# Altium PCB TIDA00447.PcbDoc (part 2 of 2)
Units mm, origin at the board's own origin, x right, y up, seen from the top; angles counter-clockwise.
Board outline 98 x 65 mm, 2 copper layers (Top Layer, Bottom Layer); 127 components, 100 nets, 389 pads, 331 vias.
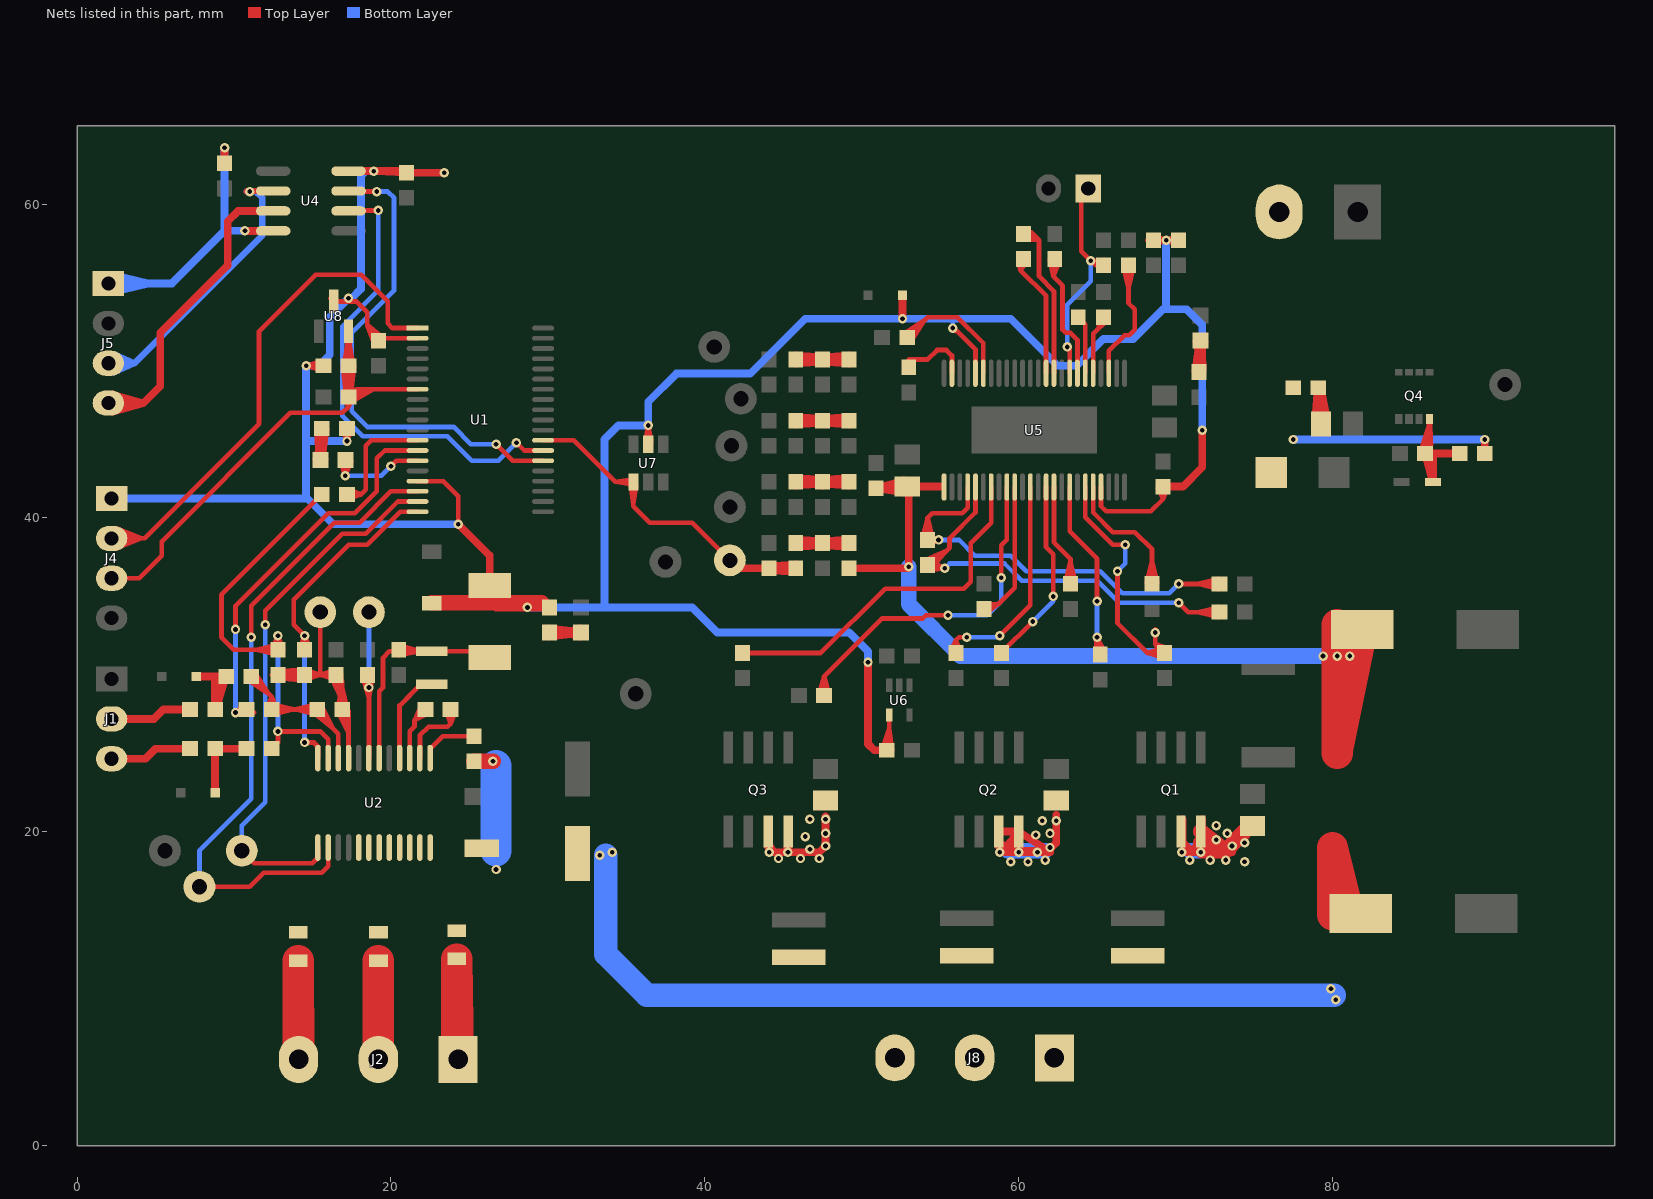
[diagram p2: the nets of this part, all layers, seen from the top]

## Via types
v1: diameter 0.6, hole 0.3, Top Layer to Bottom Layer, 323 vias
v2: diameter 0.5, hole 0.2, Top Layer to Bottom Layer, tented top, 8 vias

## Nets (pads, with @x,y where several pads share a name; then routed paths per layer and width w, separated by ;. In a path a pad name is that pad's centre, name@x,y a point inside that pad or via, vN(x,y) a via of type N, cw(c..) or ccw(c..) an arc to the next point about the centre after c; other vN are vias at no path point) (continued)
M1_SN1: C27.1 R8.1 U5.29 | length 42.9
  Top Layer w0.3: C27.1@54.037,37.306 55.422,37.922 ; C27.1@54.196,36.65 v1(55.3,36.8) ; C27.1@54.2,36.975 v1(55.3,36.8) ; C27.1@54.2,37 54.5,37.3 54.8,37.3 ; C27.1@54.297,37.285 v1(55.3,36.8) ; C27.1@54.419,36.785 55.422,37.922 ; C27.1@54.6,36.8 v1(55.3,36.8) ; U5.29@57.25,41.25 57.25,40.35 ; U5.29@57.25,41.975 57.25,40.35 ; v1(70.2,34.6) 70.8,34 R8.1@72.8,34 ; R8.1@72.737,33.677 71.4,34 ; R8.1@72.737,34.323 71.4,34 ; R8.1@72.775,34 71.4,34 ; C27.1@54.2,37.025 54.8,37.3 ; C27.1@54.2,37.025 55.422,37.922 ; C27.1@54.2,37.025 54.8,37.3 ; 54.8,37.3 54.404,36.772 54.8,37.3 ; 54.8,37.3 54.141,37.345 54.8,37.3 ; 54.8,37.3 55.6,38.1 55.6,38.7 57.25,40.35
  Bottom Layer w0.3: v1(55.3,36.8) 55.6,37.1 59.1,37.1 60.2,36 65,36 66.4,34.6 v1(70.2,34.6)
M1_SP1: C27.2 R10.1 U5.28 | length 36.1
  Top Layer w0.3: C27.2@53.877,38.663 54.2,40 ; C27.2@54.2,38.625 54.2,40 ; C27.2@54.275,38.284 v1(54.9,38.6) ; C27.2@54.275,38.916 v1(54.9,38.6) ; C27.2@54.523,38.663 54.2,40 ; U5.28@56.75,41.25 56.75,40.65 ; U5.28@56.75,41.975 56.75,40.65 ; v1(70.2,35.8) R10.1@72.8,35.8 ; R10.1@72.737,35.477 71.4,35.8 ; R10.1@72.737,36.123 71.4,35.8 ; R10.1@72.775,35.8 71.4,35.8 ; 54.2,40 54.5,40.3 56.4,40.3 56.75,40.65 ; 54.2,40 C27.2@54.2,38.6 v1(54.9,38.6)
  Bottom Layer w0.3: v1(54.9,38.6) 56.2,38.6 57.2,37.6 59.5,37.6 60.5,36.6 65.2,36.6 66.6,35.2 69.6,35.2 v1(70.2,35.8)
M2_DIR: TP4.1 U1.17 U2.14 | length 44.4
  Top Layer w0.3: TP4.1@7.8,16.5 11,16.5 11.9,17.4 15.6,17.4 16,17.8 ; v1(11.1,32.4) 11.1,34.4 16.4,39.7 18,39.7 20,41.7 U1.17@21.7,41.7 ; U2.14@16,18.325 16,17.8 ; U2.14@16,19 16,17.8 ; 20.1,41.7 U1.17@21.15,41.7
  Bottom Layer w0.3: TP4.1@7.8,16.5 7.8,18.8 11.1,22.1 v1(11.1,32.4)
M2_FG: R4.1 U1.19 U2.12 | length 25.8
  Top Layer w0.3: R4.1@14.181,31.685 v1(14.5,32.5) ; v1(14.5,25.7) 15.1,25.7 ; R4.1@14.5,31.6 v1(14.5,32.5) ; R4.1@14.5,31.625 v1(14.5,32.5) ; R4.1@14.819,31.685 v1(14.5,32.5) ; U2.12@15.35,24.7 15.35,25.45 15.1,25.7 ; U2.12@15.35,25.375 15.1,25.7 ; U1.19@21.15,40.4 20.6,40.4 ; U1.19@21.7,40.4 20.6,40.4 ; v1(14.5,32.5) 13.8,33.2 13.8,34.8 17.3,38.3 18.5,38.3 20.6,40.4
  Bottom Layer w0.3: v1(14.5,25.7) v1(14.5,32.5)
M2_SCL: R6.1 U1.13 | length 28.1
  Top Layer w0.3: v1(10.1,32.9) 10.1,34.4 16,40.3 17.7,40.3 19.1,41.7 19.1,43.8 19.6,44.3 U1.13@21.7,44.3 ; R6.1@10.613,28.082 v1(10.1,27.6) ; R6.1@10.775,27.8 v1(10.1,27.6) ; R6.1@10.793,27.475 v1(10.1,27.6) ; R6.1@11.3,27.6 v1(10.1,27.6) ; 20.1,44.3 U1.13@21.15,44.3
  Bottom Layer w0.3: v1(10.1,27.6) v1(10.1,32.9)
M2_SDA: R5.1 U1.12 | length 11.2
  Top Layer w0.3: R5.1@17.2,41.5 18.1,41.5 ; R5.1@17.225,41.5 18.1,41.5 ; R5.1@17.285,41.181 18.1,41.5 ; R5.1@17.285,41.819 18.1,41.5 ; 20.1,44.95 U1.12@21.15,44.95 ; U1.12@21.7,44.95 18.75,44.95 18.4,44.6 18.4,41.8 18.1,41.5
M2_SPEED: TP5.1 U1.18 U2.13 | length 35.7
  Top Layer w0.3: TP5.1@10.5,18.8 11.3,18 15,18 ; v1(12,33.2) 12,34.1 16.9,39 18.4,39 20.45,41.05 ; U2.13@15.35,18.325 15,18 ; U2.13@15.35,19 15.35,18.35 15,18 ; U1.18@21.15,41.05 20.45,41.05 ; U1.18@21.7,41.05 20.45,41.05
  Bottom Layer w0.3: TP5.1@10.5,18.8 10.5,20.4 12,21.9 v1(12,33.2)
M2_U: J2.3 L4.2 | length 24.1
  Top Layer w2: J2.3@14.12,5.5 J2.3@14.1,5.52 ; J2.3@14.1,5.52 L4.2@14.1,11.8 ; J2.3@14.1,5.52 14.1,11.2 ; 14.1,11.2 14.12,5.75 L4.2@14.1,11.8 ; 14.1,11.2 L4.2@14.1,11.8
M2_V: J2.2 L3.2 | length 24.1
  Top Layer w2: 19.2,11.2 19.2,5.75 L3.2@19.2,11.8 ; 19.2,11.2 L3.2@19.2,11.8 ; 19.2,11.2 J2.2@19.2,5.5 L3.2@19.2,11.8
M2_W: J2.1 L2.2 | length 24.4
  Top Layer w2: J2.1@24.28,5.5 J2.1@24.2,5.58 ; J2.1@24.2,5.58 L2.2@24.2,11.9 ; J2.1@24.2,5.58 24.2,11.2 ; 24.2,11.2 24.28,5.75 L2.2@24.2,11.9 ; 24.2,11.2 L2.2@24.2,11.9
NetC4_2: C4.2 U2.1 | length 3.7
  Top Layer w0.3: U2.1@22.5,24.7 22.5,25.3 23.3,26.1 C4.2@25.3,26.1
NetC5_1: C5.1 U2.2 | length 8.1
  Top Layer w0.3: U2.2@21.85,24.7 21.85,26.15 ; U2.2@21.85,25.375 21.85,26.15 ; C5.1@23.48,27.741 23.8,26.9 ; C5.1@24.12,27.741 23.8,26.9 ; 21.85,26.15 22.4,26.7 23.6,26.7 23.8,26.9 ; 23.8,26.9 C5.1@23.8,27.8 23.8,26.9
NetC5_2: C5.2 U2.3 | length 6.8
  Top Layer w0.3: C5.2@21.907,27.983 21.5,27.1 ; C5.2@22.175,27.8 21.5,27.1 ; C5.2@22.2,27.8 21.5,27.1 ; C5.2@22.368,27.538 21.5,27.1 ; 21.2,26.4 21.2,25.375 21.2,25.6 21.2,26.4 ; 21.2,26.4 21.5,26.7 21.5,27.1
NetC7_2: C7.2 TP3.1 U2.7 | length 15.4
  Top Layer w0.3: C7.2@18.181,29.914 18.6,28.59 ; C7.2@18.5,29.975 18.6,28.59 ; C7.2@18.5,30 18.6,29.9 U2.7@18.6,24.7 ; U2.7@18.6,25.375 18.6,26.45 ; C7.2@18.825,29.96 18.6,28.59
  Bottom Layer w0.3: v1(18.6,29.2) TP3.1@18.6,34
NetC19_1: C19.1 U5.10 | length 17.6
  Top Layer w0.3: C19.1@60.1,58.2 60.8,58.2 ; C19.1@60.234,57.757 61.3,57.7 ; C19.1@60.3,58.075 61.3,57.7 ; C19.1@60.459,58.358 61.3,57.7 ; U5.10@62.25,49.225 62.25,54.45 61.3,55.4 61.3,57.7 ; U5.10@62.25,49.95 62.25,51 ; 60.8,58.2 60.3,58.125 60.8,58.2 ; 60.8,58.2 60.449,57.836 60.8,58.2 ; 60.8,58.2 60.358,58.445 60.8,58.2 ; 60.8,58.2 61.3,57.7
NetC19_2: C19.2 U5.11 | length 10.7
  Top Layer w0.3: C19.2@59.975,56.493 60.1,55.8 ; C19.2@60.1,56.1 60.1,55.8 ; C19.2@60.3,56.475 60.1,55.8 ; C19.2@60.582,56.313 60.1,55.8 ; U5.11@61.75,49.225 61.75,54.15 60.1,55.8 ; U5.11@61.75,49.95 61.75,51
NetC22_2: C22.2 U5.44 | length 13.6
  Top Layer w0.3: U5.44@64.75,41.25 64.75,40.35 ; U5.44@64.75,41.975 64.75,40.35 ; C22.2@68.177,35.863 68.5,37.2 ; C22.2@68.5,35.8 68.5,38 67.4,39.1 66,39.1 64.75,40.35 ; C22.2@68.5,35.825 68.5,37.2 ; C22.2@68.823,35.863 68.5,37.2
NetC25_2: C25.2 U5.39 | length 11.9
  Top Layer w0.3: 62.25,40.2 U5.39@62.25,41.25 ; U5.39@62.25,41.975 62.25,38.45 63.3,37.4 63.3,36.1 C25.2@63,35.8 ; C25.2@62.977,35.863 63.3,37.2 ; C25.2@63.3,35.825 63.3,37.2 ; C25.2@63.623,35.863 63.3,37.2
NetC26_2: C26.2 U5.34 | length 12.8
  Top Layer w0.3: C26.2@57.76,34.548 58.7,34.5 ; C26.2@57.8,34.2 58.1,34.5 58.7,34.5 ; C26.2@57.8,34.225 58.7,34.5 ; C26.2@57.947,33.935 58.7,34.5 ; 59.75,40.2 U5.34@59.75,41.25 ; U5.34@59.75,41.975 59.75,35.55 58.7,34.5
NetC29_1: C29.1 R26.2 | length 16.3
  Top Layer w0.3: R26.2@79.1,48.3 R26.2@79.268,48.132
  Top Layer w0.5: C29.1@78.885,46.203 R26.2@79.268,48.132 ; C29.1@78.903,46.292 R26.2@79.075,48.3 ; C29.1@79.268,46 R26.2@79.268,48.132 ; C29.1@79.268,46.165 R26.2@79.268,48.132 ; C29.1@79.621,46.357 R26.2@79.125,48.3 ; C29.1@79.651,46.203 R26.2@79.268,48.132 ; R26.2@79.125,48.3 79.268,46.298 R26.2@79.125,48.3
NetC32_1: C32.1 U5.23 | length 4.7
  Top Layer w0.3: 53,50.1 54.2,50.1 54.8,50.7 55.4,50.7 55.75,50.35 ; U5.23@55.75,49.225 55.75,50.35 ; U5.23@55.75,49.95 55.75,50.35
NetC33_1: C33.1 U5.19 | length 13.7
  Top Layer w0.3: C33.1@52.718,51.75 54.011,52.611 ; C33.1@52.9,51.5 54.2,52.8 56.1,52.8 57.75,51.15 U5.19@57.75,49.225 ; C33.1@52.925,51.5 54.011,52.611 ; C33.1@53.18,51.298 54.011,52.611 ; U5.19@57.75,49.95 57.75,51
NetD1_1: D1.1 U1.14 | length 9.8
  Top Layer w0.3: D1.1@16.765,43.645 v1(17.1,42.7) ; D1.1@17.469,43.632 v1(17.1,42.7) ; v1(20,43.3) 20.35,43.65 ; U1.14@21.15,43.65 20.35,43.65 ; U1.14@21.7,43.65 20.35,43.65 ; v1(17.1,42.7) D1.1@17.118,43.703 17.1,43.685 v1(17.1,42.7)
  Bottom Layer w0.3: v1(17.1,42.7) 19.4,42.7 v1(20,43.3)
NetD1_2: D1.2 R7.1 | length 21.4
  Top Layer w0.3: D1.2@15.163,43.748 15.518,45.111 ; R7.1@15.251,45.675 15.518,44.32 ; R7.1@15.251,45.723 15.316,44.337 ; R7.1@15.306,45.637 D1.2@15.756,44.197 ; D1.2@15.518,43.703 15.518,45.618 R7.1@15.6,45.7 ; D1.2@15.6,43.8 D1.2@15.7,43.7 ; R7.1@15.625,45.7 D1.2@15.756,44.197 ; D1.2@15.873,43.748 15.518,45.111 ; R7.1@15.885,45.602 15.316,44.337 ; R7.1@15.896,45.648 15.518,44.32 ; R7.1@15.95,45.693 D1.2@15.756,44.197 ; 15.316,44.337 R7.1@15.575,45.7 ; 15.518,44.32 R7.1@15.575,45.7 ; 15.518,45.111 R7.1@15.575,45.7 ; 15.518,45.111 15.255,45.641 15.518,45.111 ; 15.518,45.111 15.877,45.581 15.518,45.111 ; 15.518,45.111 R7.1@15.575,45.7
NetD3_1: D3.1 R11.2 R12.1 | length 14.5
  Top Layer w0.5: 8.8,23.325 R11.2@8.8,25.3 ; 8.8,24.3 D3.1@8.8,22.5 R11.2@8.8,25.3 ; R11.2@8.8,25.3 10.775,25.3 8.825,25.3 R12.1@10.8,25.3 R11.2@8.8,25.3
NetD4_1: D4.1 R13.1 R14.2 | length 15.7
  Top Layer w0.3: R13.1@9.352,30.201 8.8,29.8 ; R13.1@9.383,29.588 8.9,29.9 ; R13.1@9.383,30.212 8.9,29.9 ; R13.1@9.445,29.576 8.8,29.8 ; 8.8,29.8 9.475,29.9 8.9,29.9 ; 8.8,29.8 8.9,29.9
  Top Layer w0.5: R14.2@8.825,27.8 R13.1@9.412,29.703 ; R13.1@9.5,29.9 8.9,29.9 ; 8.9,29.9 R13.1@9.475,29.9 ; 8.9,29.9 R13.1@9.475,29.9 ; 8.9,29.9 D4.1@7.6,29.9 R13.1@9.475,29.9 ; R13.1@9.475,29.9 R14.2@8.8,27.8 8.8,29.8 R13.1@9.475,29.9
NetD7_1: D7.1 Q4.4 R27.1 R29.2 | length 27.4
  Top Layer w0.4: R29.2@85.657,44.161 86.175,45.82 ; R29.2@85.703,44.262 86.175,44.675 ; 86.175,44.795 Q4.4@86.175,46.22 ; Q4.4@86.175,46.2 86.175,44.675 ; 86.189,44.795 Q4.4@86.175,46.22 ; R29.2@86.195,44.048 86.175,44.675 ; R29.2@86.199,44.082 86.175,45.82 ; 86.175,44.675 85.925,44.1 86.175,45.82 ; 86.175,45.82 Q4.4@86.175,46.22 ; 86.175,45.82 Q4.4@86.175,46.22 ; 86.175,45.82 Q4.4@86.175,46.22
  Top Layer w0.5: R29.2@85.9,44.1 R29.2@86.2,44.1 ; R29.2@85.951,44 D7.1@86.4,42.3 ; R29.2@86.05,44.25 85.9,44.4 86.175,44.675 R29.2@85.925,44.1 ; R29.2@86.1,44.1 88.075,44.1 R29.2@86.2,44.1 ; R27.1@87.9,44.1 R29.2@85.925,44.1 ; R27.1@88.1,44.1 R29.2@86.2,44.1 ; R29.2@85.925,44.1 D7.1@86.4,42.3 ; R29.2@86.2,44.1 86.4,43.9 D7.1@86.4,42.3
NetD9_2: D9.2 R31.1 | length 28.1
  Top Layer w0.3: R31.1@71.175,49.327 71.347,50.713 ; R31.1@71.177,49.363 71.5,50.7 ; R31.1@71.179,49.377 71.558,50.702 ; R31.1@71.191,49.425 71.783,50.729 ; D9.2@71.243,51.28 71.5,49.885 ; R31.1@71.5,49.3 71.5,51.2 D9.2@71.6,51.3 71.5,49.885 ; R31.1@71.817,49.398 71.347,50.713 ; R31.1@71.823,49.363 71.5,50.7 ; R31.1@71.824,49.297 71.783,50.729 ; R31.1@71.824,49.35 71.558,50.702 ; D9.2@71.951,51.23 71.5,49.885 ; R31.1@71.189,49.419 71.5,49.885 ; R31.1@71.189,49.419 71.5,49.885 ; R31.1@71.189,49.419 71.5,49.885 ; 71.347,50.713 R31.1@71.5,49.325 ; R31.1@71.5,49.325 71.5,49.885 ; R31.1@71.5,49.325 71.558,50.702 ; R31.1@71.5,49.325 71.5,49.885 ; R31.1@71.5,49.325 71.5,49.885 ; R31.1@71.5,49.325 71.783,50.729 ; R31.1@71.5,49.325 71.5,50.7 ; 71.5,49.885 R31.1@71.811,49.419 ; 71.5,49.885 R31.1@71.811,49.419 ; 71.5,49.885 R31.1@71.811,49.419
NetD10_2: D10.2 R32.1 | length 24.9
  Top Layer w0.3: R32.1@30.095,32.35 31.501,32.489 ; R32.1@30.095,33.05 31.501,32.911 ; R32.1@30.1,32.675 31.501,32.489 ; R32.1@30.1,32.725 31.501,32.911 ; R32.1@30.179,32.41 31.501,32.911 ; R32.1@30.179,32.99 31.501,32.489 ; D10.2@32.054,32.345 30.692,32.7 ; D10.2@32.054,33.055 30.692,32.7 ; R32.1@30.1,32.7 30.692,32.7 ; R32.1@30.1,32.7 30.692,32.7 ; R32.1@30.1,32.7 D10.2@32.1,32.7 30.692,32.7 ; R32.1@30.189,32.387 30.692,32.7 ; R32.1@30.189,32.387 30.692,32.7 ; R32.1@30.189,32.387 30.692,32.7 ; R32.1@30.189,33.013 30.692,32.7 ; R32.1@30.189,33.013 30.692,32.7 ; R32.1@30.189,33.013 30.692,32.7 ; 31.475,32.7 30.138,32.377 31.475,32.7 ; 31.475,32.7 30.138,33.023 31.475,32.7
NetJ1_2: J1.2 R14.1 | length 6.9
  Top Layer w0.5: J1.2@2.2,27.2 4.9,27.2 5.5,27.8 ; R14.1@7.175,27.8 5.5,27.8 ; R14.1@7.2,27.8 5.5,27.8
NetJ1_3: J1.3 R11.1 | length 7.2
  Top Layer w0.5: J1.3@2.2,24.66 4.36,24.66 5,25.3 R11.1@7.2,25.3 ; 5.2,25.3 R11.1@7.175,25.3
NetJ8_1: J8.1 L5.2
NetJ8_2: J8.2 L6.2
NetJ8_3: J8.3 L7.2
NetJ10_1: J10.1 R30.2 U5.8 | length 17.1
  Top Layer w0.3: v1(63.1,50.9) v1@63.25,50.75 ; U5.8@63.25,49.225 v1@63.25,50.75 ; U5.8@63.25,49.95 v1@63.25,50.75 ; J10.1@64.44,60.9 64,60.46 64,57 v1(64.6,56.4) ; R30.2@65.237,55.844 v1(64.6,56.4) ; R30.2@65.4,56.1 65.1,56.4 v1(64.6,56.4) ; R30.2@65.4,56.125 v1(64.6,56.4) ; R30.2@65.445,56.447 v1(64.6,56.4)
  Bottom Layer w0.3: v1(63.1,50.9) 63.1,53.6 64.6,55.1 v1(64.6,56.4)
NetL1_2: L1.2 U2.4 | length 8.3
  Top Layer w0.3: U2.4@20.55,24.7 20.55,28.05 L1.2@21.9,29.4 ; U2.4@20.55,25.375 20.55,26.45 ; 20.99,28.49 L1.2@21.9,29.4 ; L1.2@22.6,29.4 L1.2@21.9,29.4
NetL2_1: L2.1 U2.21 U2.22
NetL3_1: L3.1 U2.19 U2.20
NetL4_1: L4.1 U2.17 U2.18
NetR15_2: R15.2 U5.7 | length 12
  Top Layer w0.3: R15.2@61.976,56.456 62.2,55.4 ; R15.2@62.2,56.1 62.2,55.4 ; R15.2@62.3,56.475 62.2,55.4 ; R15.2@62.615,56.397 62.2,55.4 ; U5.7@63.75,49.225 63.75,51.35 63.3,51.8 63,51.8 62.8,52 62.8,54.8 62.2,55.4 ; U5.7@63.75,49.95 63.75,51
NetR18_2: R18.2 U5.5 | length 7.1
  Top Layer w0.3: U5.5@64.75,49.225 64.75,51.75 65.1,52.1 ; U5.5@64.75,49.95 64.75,51 ; R18.2@65.081,52.838 65.1,52.1 ; R18.2@65.4,52.775 65.1,52.1 ; R18.2@65.4,52.8 65.1,52.5 65.1,52.1 ; R18.2@65.661,52.581 65.1,52.1
NetR19_2: R19.2 U5.3 | length 12.7
  Top Layer w0.3: U5.3@65.75,49.225 65.75,50.65 ; U5.3@65.75,49.95 65.75,50.65 ; R19.2@66.677,56.037 67,54.7 ; R19.2@67,56.075 67,54.7 ; R19.2@67,56.1 67,53.7 67.4,53.3 67.4,52 67.05,51.65 66.75,51.65 65.75,50.65 ; R19.2@67.323,56.037 67,54.7
NetR20_1: R20.1 U5.43 | length 22.7
  Top Layer w0.3: 64.25,40.2 U5.43@64.25,41.25 ; U5.43@64.25,41.975 64.25,40.05 66,38.3 v1(66.8,38.3) ; v1(66.3,36.6) 66.3,33.3 68.2,31.4 ; v1(68.7,32.7) 68.7,32 ; v1@68.7,32.9 v1@68.8,32.8 ; R20.1@69.034,31.239 68.7,32 ; R20.1@69.252,31.079 68.2,31.4 ; R20.1@69.252,31.721 68.2,31.4 ; R20.1@69.3,31.425 68.7,32 ; R20.1@69.475,31.699 68.7,32 ; 68.2,31.4 R20.1@69.3,31.4 ; 68.2,31.4 R20.1@69.3,31.4 ; 68.7,32 R20.1@69.3,31.4
  Bottom Layer w0.3: v1(66.3,36.6) 66.8,37.1 v1(66.8,38.3)
NetR21_1: R21.1 U5.41 | length 15.8
  Top Layer w0.3: 63.25,40.2 U5.41@63.25,41.25 ; U5.41@63.25,41.975 63.25,39.15 65,37.4 v1(65,34.7) ; R21.1@64.875,31.314 v1(65,32.4) ; R21.1@65.2,31.3 65,31.5 v1(65,32.4) ; R21.1@65.2,31.325 v1(65,32.4) ; R21.1@65.507,31.431 v1(65,32.4)
  Bottom Layer w0.3: v1(65,32.4) v1(65,34.7)
NetR22_1: R22.1 U5.38 | length 13.2
  Top Layer w0.3: R22.1@58.9,31.4 v1(60.9,33.4) ; 61.75,40.2 U5.38@61.75,41.25 ; U5.38@61.75,41.975 61.75,38.15 62.2,37.7 v1(62.2,35)
  Bottom Layer w0.3: v1(60.9,33.4) 62.2,34.7 v1(62.2,35)
NetR23_1: R23.1 U5.36 | length 17.4
  Top Layer w0.3: R23.1@55.682,31.493 56,32.2 ; R23.1@56,31.4 56,32.2 ; R23.1@56,31.425 56,32.2 ; R23.1@56.318,31.493 56,32.2 ; v1(56.7,32.4) 56.2,32.4 56,32.2 ; v1(58.8,32.5) 60.75,34.45 U5.36@60.75,41.975 ; 60.75,40.2 U5.36@60.75,41.25
  Bottom Layer w0.3: v1(56.7,32.4) 58.7,32.4 v1(58.8,32.5)
NetR25_1: R25.1 U5.33 | length 25.4
  Top Layer w0.3: R25.1@47.278,28.744 47.6,29.9 ; R25.1@47.6,28.7 47.6,29.9 ; R25.1@47.922,28.744 47.6,29.9 ; v1(55.5,33.8) 54.1,33.8 53.9,33.6 51.3,33.6 47.6,29.9 ; v1(58.9,36.2) 58.9,38.25 59.25,38.6 U5.33@59.25,41.975 ; 59.25,40.2 U5.33@59.25,41.25
  Bottom Layer w0.3: v1(55.5,33.8) 58,33.8 58.9,34.7 v1(58.9,36.2)
NetR28_1: R28.1 U5.31 | length 24
  Top Layer w0.3: R28.1@42.4,31.4 47.4,31.4 51.5,35.5 56.5,35.5 56.95,35.95 56.95,38.4 58.25,39.7 U5.31@58.25,41.975 ; 58.25,40.2 U5.31@58.25,41.25
NetR33_1: R33.1 R37.1 R41.2 | length 38
  Top Layer w0.3: R37.1@45.785,45.85 R41.2@47.171,45.947 ; R37.1@45.785,46.55 R41.2@47.171,46.453 ; R37.1@45.8,46.175 R41.2@47.171,45.947 ; R37.1@45.8,46.225 R41.2@47.171,46.453 ; R37.1@45.89,45.913 R41.2@47.171,46.453 ; R37.1@45.89,46.487 R41.2@47.171,45.947 ; R41.2@47.462,45.877 R37.1@46.125,46.2 ; R41.2@47.462,46.523 R37.1@46.125,46.2 ; R41.2@47.5,46.2 R37.1@46.125,46.2 ; R41.2@47.538,45.877 48.875,46.2 R41.2@47.538,46.523 ; R33.1@49.11,45.913 R41.2@47.829,46.453 ; R33.1@49.11,46.487 R41.2@47.829,45.947 ; R33.1@49.162,45.877 R41.2@47.825,46.2 ; R33.1@49.162,46.523 R41.2@47.825,46.2 ; R33.1@49.2,46.175 R41.2@47.829,45.947 ; R33.1@49.2,46.225 R41.2@47.829,46.453 ; R33.1@49.215,45.85 R41.2@47.829,45.947 ; R33.1@49.215,46.55 R41.2@47.829,46.453 ; R41.2@47.175,46.2 R37.1@45.8,46.2 R33.1@49.2,46.2 R41.2@47.825,46.2 ; R41.2@47.175,46.2 45.838,45.877 R41.2@47.175,46.2 ; R41.2@47.175,46.2 45.838,46.523 R41.2@47.175,46.2
NetR34_1: R34.1 R38.1 R42.2 | length 38
  Top Layer w0.3: R38.1@45.785,41.95 R42.2@47.171,42.047 ; R38.1@45.785,42.65 R42.2@47.171,42.553 ; R38.1@45.8,42.275 R42.2@47.171,42.047 ; R38.1@45.8,42.325 R42.2@47.171,42.553 ; R38.1@45.89,42.013 R42.2@47.171,42.553 ; R38.1@45.89,42.587 R42.2@47.171,42.047 ; R42.2@47.462,41.977 R38.1@46.125,42.3 ; R42.2@47.462,42.623 R38.1@46.125,42.3 ; R42.2@47.538,41.977 48.875,42.3 R42.2@47.538,42.623 ; R34.1@49.11,42.013 R42.2@47.829,42.553 ; R34.1@49.11,42.587 R42.2@47.829,42.047 ; R34.1@49.162,41.977 R42.2@47.825,42.3 ; R34.1@49.162,42.623 R42.2@47.825,42.3 ; R34.1@49.2,42.275 R42.2@47.829,42.047 ; R34.1@49.2,42.325 R42.2@47.829,42.553 ; R34.1@49.215,41.95 R42.2@47.829,42.047 ; R34.1@49.215,42.65 R42.2@47.829,42.553 ; R38.1@46.125,42.3 R42.2@47.5,42.3 ; R42.2@47.175,42.3 R38.1@45.8,42.3 R42.2@47.5,42.3 ; R42.2@47.175,42.3 45.838,41.977 R42.2@47.175,42.3 ; R42.2@47.175,42.3 45.838,42.623 R42.2@47.175,42.3 ; R42.2@47.5,42.3 R34.1@49.2,42.3 R42.2@47.825,42.3
NetR35_1: R35.1 R39.1 R43.2 | length 38
  Top Layer w0.3: R39.1@45.785,49.75 R43.2@47.171,49.847 ; R39.1@45.785,50.45 R43.2@47.171,50.353 ; R39.1@45.8,50.075 R43.2@47.171,49.847 ; R39.1@45.8,50.125 R43.2@47.171,50.353 ; R39.1@45.89,49.813 R43.2@47.171,50.353 ; R39.1@45.89,50.387 R43.2@47.171,49.847 ; R43.2@47.462,49.777 R39.1@46.125,50.1 ; R43.2@47.462,50.423 R39.1@46.125,50.1 ; R43.2@47.538,49.777 48.875,50.1 R43.2@47.538,50.423 ; R35.1@49.11,49.813 R43.2@47.829,50.353 ; R35.1@49.11,50.387 R43.2@47.829,49.847 ; R35.1@49.162,49.777 R43.2@47.825,50.1 ; R35.1@49.162,50.423 R43.2@47.825,50.1 ; R35.1@49.2,50.075 R43.2@47.829,49.847 ; R35.1@49.2,50.125 R43.2@47.829,50.353 ; R35.1@49.215,49.75 R43.2@47.829,49.847 ; R35.1@49.215,50.45 R43.2@47.829,50.353 ; R39.1@46.125,50.1 R43.2@47.5,50.1 ; R43.2@47.175,50.1 R39.1@45.8,50.1 R43.2@47.5,50.1 ; R43.2@47.175,50.1 45.838,49.777 R43.2@47.175,50.1 ; R43.2@47.175,50.1 45.838,50.423 R43.2@47.175,50.1 ; R43.2@47.5,50.1 R35.1@49.2,50.1 R43.2@47.825,50.1
NetR36_1: R36.1 R40.1 R44.2 | length 38
  Top Layer w0.3: R40.1@45.785,38.05 R44.2@47.171,38.147 ; R40.1@45.785,38.75 R44.2@47.171,38.653 ; R40.1@45.8,38.375 R44.2@47.171,38.147 ; R40.1@45.8,38.425 R44.2@47.171,38.653 ; R40.1@45.89,38.113 R44.2@47.171,38.653 ; R40.1@45.89,38.687 R44.2@47.171,38.147 ; R44.2@47.462,38.077 R40.1@46.125,38.4 ; R44.2@47.462,38.723 R40.1@46.125,38.4 ; R44.2@47.5,38.4 R40.1@46.125,38.4 ; R44.2@47.538,38.077 48.875,38.4 R44.2@47.538,38.723 ; R36.1@49.11,38.113 R44.2@47.829,38.653 ; R36.1@49.11,38.687 R44.2@47.829,38.147 ; R36.1@49.162,38.077 R44.2@47.825,38.4 ; R36.1@49.162,38.723 R44.2@47.825,38.4 ; R36.1@49.2,38.375 R44.2@47.829,38.147 ; R36.1@49.2,38.425 R44.2@47.829,38.653 ; R36.1@49.215,38.05 R44.2@47.829,38.147 ; R36.1@49.215,38.75 R44.2@47.829,38.653 ; R44.2@47.175,38.4 R40.1@45.8,38.4 R36.1@49.2,38.4 R44.2@47.825,38.4 ; R44.2@47.175,38.4 45.838,38.077 R44.2@47.175,38.4 ; R44.2@47.175,38.4 45.838,38.723 R44.2@47.175,38.4
NetR45_2: R45.2 U5.6 | length 4.8
  Top Layer w0.3: R45.2@63.8,52.8 64.25,52.35 U5.6@64.25,49.225 ; U5.6@64.25,49.95 64.25,51
NUC_SBWTDIO: C13.1 J4.3 R9.1 U1.7 U8.2 | length 69
  Top Layer w0.3: J4.3@2.2,36.16 3.96,36.16 5.4,37.6 5.4,38.5 13.6,46.7 16.9,46.7 17.3,47.1 ; R9.1@16.95,49.7 17.112,48.295 ; C13.1@16.977,47.738 17.3,49.075 ; R9.1@16.977,49.662 17.3,48.325 ; R9.1@16.977,49.738 17.3,51.075 ; R9.1@17.009,49.626 17.488,48.295 ; 17.095,50.225 U8.2@17.3,51.45 ; C13.1@17.256,48.018 18.868,48.2 ; R9.1@17.275,49.7 17.112,48.295 ; R9.1@17.3,49.5 C13.1@17.3,47.7 ; 17.3,50.25 U8.2@17.3,51.45 ; U8.2@17.3,52.2 U8.2@17.3,51.9 R9.1@17.3,49.7 ; R9.1@17.325,49.7 17.488,48.295 ; C13.1@17.456,47.402 18.868,48.2 ; 17.505,50.225 U8.2@17.3,51.45 ; R9.1@17.591,49.626 17.112,48.295 ; C13.1@17.623,47.738 17.3,49.075 ; R9.1@17.623,49.662 17.3,48.325 ; R9.1@17.623,49.738 17.3,51.075 ; R9.1@17.65,49.7 17.488,48.295 ; 20.1,48.2 U1.7@21.15,48.2 ; U1.7@21.7,48.2 17.8,48.2 ; 17.3,47.1 C13.1@17.3,47.7 ; 17.3,47.1 16.987,47.612 17.3,47.1 ; 17.3,47.1 17.613,47.612 17.3,47.1 ; 17.3,47.1 C13.1@17.3,47.7 ; C13.1@17.3,47.7 17.8,48.2 ; 17.3,48.325 R9.1@17.3,49.7 ; 17.3,49.075 R9.1@17.3,49.7 ; 17.3,49.075 16.986,49.616 17.3,49.075 ; 17.3,49.075 17.614,49.616 17.3,49.075 ; 17.3,49.075 R9.1@17.3,49.7 ; 17.3,51.075 U8.2@17.3,51.45 ; 17.3,51.075 U8.2@17.3,51.45 ; C13.1@17.325,47.7 17.8,48.2 ; C13.1@17.325,47.7 18.868,48.2 ; C13.1@17.325,47.7 17.8,48.2 ; 17.8,48.2 17.607,47.538 17.8,48.2 ; 17.8,48.2 17.149,47.973 17.8,48.2
RX_ISO: J5.4 U4.3 | length 26.7
  Top Layer w0.5: J5.4@2,47.32 4.22,47.32 ; J5.4@2.2,47.32 4.22,47.32 ; J5.4@2.275,46.775 4.22,47.32 ; J5.4@2.275,47.865 4.22,47.32 ; U4.3@11.7,59.565 10.265,59.565 ; U4.3@12.5,59.565 10.265,59.565 ; 4.22,47.32 5.3,48.4 5.3,51.8 9.6,56.1 9.6,58.9 10.265,59.565
SCL: R3.1 R6.2 R13.2 U2.10 | length 29.3
  Top Layer w0.3: R13.2@10.918,29.65 12.211,28.789 ; R13.2@11.1,29.9 12.4,28.6 ; R13.2@11.125,29.9 12.211,28.789 ; R13.2@11.38,30.102 12.211,28.789 ; R6.2@12.082,27.866 12.4,28.6 ; R6.2@12.425,27.8 13.8,27.8 ; R6.2@12.463,27.477 13.8,27.8 ; R6.2@12.463,28.123 13.8,27.8 ; R6.2@12.718,27.866 12.4,28.6 ; R3.1@15.096,27.57 16.288,26.612 ; R3.1@15.237,27.477 13.9,27.8 ; R3.1@15.237,28.123 13.9,27.8 ; R3.1@15.275,27.8 13.9,27.8 ; R3.1@15.325,27.8 16.288,26.612 ; R3.1@15.598,27.977 16.288,26.612 ; R6.2@12.4,27.9 12.5,27.8 R3.1@15.3,27.8 15.3,27.6 16.65,26.25 ; R6.2@12.4,27.9 12.4,28.6 ; R6.2@12.4,27.9 R6.2@12.4,27.8 12.4,28.6 ; 16.65,26.25 16.65,25.375 16.65,25.6 16.65,26.25
SDA: R2.1 R5.2 R12.2 U2.11 | length 35.8
  Top Layer w0.3: R12.2@12.4,25.3 12.8,25.7 v1(12.8,26.4) 15.5,26.4 16,25.9 ; R2.1@12.481,31.685 v1(12.8,32.5) ; R2.1@12.762,31.277 11.425,31.6 ; R2.1@12.762,31.923 11.425,31.6 ; R2.1@12.8,31.625 v1(12.8,32.5) ; R2.1@13.119,31.685 v1(12.8,32.5) ; R5.2@15.6,41.5 9.2,35.1 9.2,32.4 10,31.6 R2.1@12.8,31.6 ; U2.11@16,24.7 16,25.9 ; U2.11@16,25.375 16,25.9 ; 11.425,31.6 R2.1@12.8,31.6 ; R2.1@12.8,31.6 v1(12.8,32.5)
  Bottom Layer w0.3: v1(12.8,26.4) v1(12.8,32.5)
SGND: C11.2 J5.1 U4.4 | length 27.1
  Top Layer w0.5: C11.2@9.4,62.6 v1(9.4,63.6) C11.2@9.4,62.625 ; U4.4@11.7,58.295 10.7,58.295 U4.4@12.5,58.295
  Bottom Layer w0.5: J5.1@2,54.94 6.04,54.94 9.4,58.3 ; J5.1@2.2,54.94 4.5,54.94 ; J5.1@2.266,54.394 4.5,54.94 ; J5.1@2.266,55.486 4.5,54.94 ; v1(9.4,63.6) 9.4,58.3 ; v1(10.7,58.3) 9.4,58.3
TX_ISO: J5.3 U4.2 | length 23.7
  Top Layer w0.4: v1@10.8,60.8 v1@10.835,60.835 ; U4.2@11.7,60.835 v1@10.835,60.835 ; U4.2@12.5,60.835 v1@10.835,60.835
  Bottom Layer w0.4: J5.3@2,49.86 3.66,49.86 ; J5.3@2.2,49.86 3.66,49.86 ; J5.3@2.323,49.273 3.66,49.86 ; J5.3@2.323,50.447 3.66,49.86 ; v1@10.8,60.8 v1(11,60.8) 11.4,60.8 11.8,60.4 11.8,58 3.66,49.86
UART_RX: U1.26 U4.6 | length 31.3
  Top Layer w0.3: U4.6@17.3,59.565 17.335,59.6 v1(19.2,59.6) ; v1(28,44.8) 28.5,44.3 ; U1.26@29.15,44.3 28.5,44.3 ; U1.26@29.7,44.3 28.5,44.3
  Bottom Layer w0.3: v1(19.2,59.6) 19.2,54.5 16.9,52.2 16.9,46.5 18.2,45.2 23.6,45.2 25.15,43.65 26.85,43.65 v1(28,44.8)
UART_TX: U1.25 U4.7 | length 33.4
  Top Layer w0.3: U4.7@17.3,60.835 17.335,60.8 v1(19.1,60.8) U4.7@18.1,60.835 ; v1(26.7,44.7) 27.75,43.65 U1.25@29.7,43.65 ; 28.1,43.65 U1.25@29.15,43.65
  Bottom Layer w0.3: v1(19.1,60.8) 19.8,60.8 20.2,60.4 20.2,54.5 17.5,51.8 17.5,46.8 18.5,45.8 24,45.8 25.1,44.7 v1(26.7,44.7)
UC_SBWTCK: J4.2 U1.1 | length 41.7
  Top Layer w0.3: J4.2@2.2,38.7 4.3,38.7 11.6,46 11.6,51.9 15.2,55.5 18.1,55.5 19.8,53.8 19.8,52.4 20.1,52.1 ; J4.2@2.4,38.7 4.1,38.7 ; J4.2@2.436,38.352 4.1,38.7 ; J4.2@2.436,39.048 4.1,38.7 ; J4.2@2.524,38.062 4.1,38.7 ; J4.2@2.524,39.338 4.1,38.7 ; U1.1@21.15,52.1 20.1,52.1 ; U1.1@21.7,52.1 20.1,52.1
V3P3: C6.1 R2.2 R3.2 R4.2 TP2.1 U2.9 | length 47.5
  Top Layer w0.3: R2.2@12.4,30 R2.2@12.8,30 R4.2@14.5,30 ; R2.2@12.838,29.677 14.175,30 R2.2@12.838,30.323 ; R4.2@14.41,29.713 R2.2@13.129,30.253 ; R4.2@14.41,30.287 R2.2@13.129,29.747 ; R4.2@14.462,29.677 R2.2@13.125,30 ; R4.2@14.462,30.323 R2.2@13.125,30 ; R4.2@14.5,29.975 R2.2@13.129,29.747 ; R4.2@14.5,30.025 R2.2@13.129,30.253 ; R4.2@14.515,29.65 R2.2@13.129,29.747 ; R4.2@14.515,30.35 R2.2@13.129,30.253 ; R4.2@14.553,29.679 15.5,30 ; R4.2@14.553,30.321 15.5,30 ; TP2.1@14.8,34 15.5,33.3 15.5,30 ; C6.1@16.194,29.865 16.9,28.375 ; C6.1@16.447,29.679 15.5,30 ; C6.1@16.447,30.321 15.5,30 ; C6.1@16.5,29.975 16.9,28.375 ; R3.2@16.577,27.838 16.9,29.175 R3.2@17.223,27.838 ; R3.2@16.62,27.689 17.3,26.295 ; C6.1@16.822,30.022 16.9,28.375 ; R3.2@16.9,27.7 R3.2@16.9,27.8 16.9,29.6 C6.1@16.5,30 ; R3.2@16.925,27.8 17.3,26.295 ; R3.2@17.247,27.845 17.3,26.295 ; U2.9@17.3,24.7 R3.2@17.3,27.7 ; U2.9@17.3,25.375 17.3,26.45 ; R2.2@13.125,30 R4.2@14.5,30 ; R4.2@14.5,30 15.5,30 ; 15.5,30 C6.1@16.5,30 ; 15.5,30 C6.1@16.5,30
VM: C3.2 C4.1 C8.1 C14.1 C15.1 C16.2 C17.2 C18.2 C21.1 C28.1 D5.2 J9.2 Q1.7 Q1.8 Q2.7 Q2.8 Q3.7 Q3.8 R26.1 R27.2 R36.2 U2.23 U2.24 U5.25 | length 207.7
  Top Layer w0.5: Q3.7@44.035,20.5 44.035,19.065 44.4,18.7 ; Q3.7@44.045,19.291 44.4,18.7 ; Q3.8@45.305,20.5 v1@45.305,18.805 ; v1@47.7,20.968 v1(47.7,20.8) v1(47.7,19.9) v1(47.7,19.1) 47.3,18.7 v1(45.3,18.7) v1@45.2,18.7 ; 49.8,36.8 v1@53,36.8 ; C15.1@52.674,42.38 C14.1@50.9,41.9 ; C15.1@52.715,41.615 C14.1@50.9,41.9 ; C15.1@52.735,42 C14.1@50.9,41.9 ; C15.1@52.9,42 55,42 ; v1(53,36.9) 53,41.7 52.8,41.9 C14.1@50.9,41.9 ; Q2.7@58.735,20.6 58.735,19.065 v1@59,18.8 ; Q2.7@58.745,20.016 Q2.8@60.015,20.016 ; 59.1,18.7 v1@59.9,18.7 ; Q2.8@60.005,19.105 Q2.8@60.005,20.6 ; 62,18.7 v1(61.2,18.7) v1(60,18.7) v1@59.9,18.7 ; 62.4,21.084 v1(62.4,20.7) 62.4,19.3 v1@61.9,18.8 ; Q1.7@70.345,19.291 71,18.8 ; Q1.7@70.435,20.8 70.435,19.365 71,18.8 ; 70.7,18.7 v1@71.5,18.7 ; Q1.8@71.705,20.8 v1@71.705,18.805 ; 73.6,18.7 v1(71.6,18.7) v1@71.5,18.7 ; C28.1@80,32.9 C28.1@80.3,33.2 ; R27.2@89.7,44.1 v1(89.7,45) ; 44.4,18.7 v1@45.2,18.7 ; v1@45.2,18.7 v1@45.305,18.805 ; v1@45.2,18.7 Q3.8@45.315,19.291 ; v1@45.305,18.805 Q3.8@45.315,19.291 ; v1@45.305,18.805 Q3.8@45.315,19.291 ; Q2.7@58.745,19.291 v1@59,18.8 ; Q2.7@58.745,19.291 v1@59,18.8 ; Q2.7@58.745,19.291 59.7,18.8 ; Q2.7@58.745,19.291 v1@59,18.8 ; v1@59,18.8 Q2.8@60.015,20.016 ; v1@59,18.8 59.7,18.8 ; 59.7,18.8 Q2.8@60.015,19.291 ; v1@59.9,18.7 60.005,18.805 Q2.8@60.015,19.291 ; v1@59.9,18.7 Q2.8@60.015,19.291 ; Q2.8@60.015,19.291 60.1,18.8 v1@61.9,18.8 ; Q2.8@60.015,20.016 v1@61.9,18.8 ; 71,18.8 v1@71.6,18.8 ; 71,18.8 Q1.8@71.615,19.291 ; v1@71.5,18.7 v1@71.6,18.8 ; v1@71.5,18.7 Q1.8@71.615,19.291 ; v1@71.6,18.8 v1@71.7,18.8 ; v1@71.6,18.8 Q1.8@71.615,19.291 ; v1@71.6,18.8 Q1.8@71.615,19.291 ; v1@71.6,18.8 Q1.8@71.615,19.291 ; v1@71.6,18.8 Q1.8@71.615,19.291 ; v1@71.6,18.8 71.605,18.805 Q1.8@71.615,19.291 ; Q1.8@71.615,19.291 v1@71.705,18.805 ; Q1.8@71.615,19.291 v1@71.7,18.8 ; Q1.8@71.615,19.291 v1@71.7,18.8 ; Q1.8@71.615,19.291 v1@71.705,18.805 ; v1@71.7,18.8 v1@71.705,18.805
  Top Layer w1: C4.1@25.3,24.5 v1(26.5,24.5) ; Q1.8@71.615,19.291 71.7,18.8 73.2,18.8 ; Q1.8@71.615,20.016 73.2,18.8 ; 73.2,18.8 74,19.6 74.735,20.384 73.2,18.8
  Top Layer w2: C21.1@80,14.7 80,19 C21.1@81.05,14.8 ; 80.3,25 C28.1@80.3,33.2 ; 80.3,25.147 C28.1@81.9,32.9
  Bottom Layer w0.5: v1(77.5,45) v1(89.7,45)
  Bottom Layer w1: v1(53,36.9) 53,34.5 56.3,31.2 v1(79.4,31.2) v1(80.3,31.2) v1(81.1,31.2) 81.6,31.2 ; 59.3,18.8 61.7,18.8 ; 70.9,18.8 v1@71.5,18.8
  Bottom Layer w1.5: 33.7,18.5 33.7,12.2 36.3,9.6 80.1,9.6
  Bottom Layer w2: 26.7,18.8 26.7,24.2
  other v1: 80.2,9.3 79.9,10 26.7,17.6 59.5,18.1 60.6,18.1 74.4,18.1 61.7,18.2 70.9,18.2 72.2,18.2 73.2,18.2 44.7,18.3 46.1,18.3 47.3,18.3 33.3,18.5 34.1,18.7 44.1,18.7 58.8,18.7 70.4,18.7 46.7,18.9 62,19 73.6,19.1 74.4,19.3 72.6,19.5 46.4,19.7 61.1,19.8 62,19.9 73.3,19.9 72.6,20.4 61.5,20.7 46.7,20.8
VM_MONITOR: C37.1 R40.2 TP13.1 U1.27 U7.1 | length 51.2
  Top Layer w0.3: U1.27@29.7,44.95 31.65,44.95 34.3,42.3 ; U1.27@30.25,44.95 31.3,44.95 ; U7.1@35.275,42.063 35.45,40.85 ; U7.1@35.437,42.126 34.3,42.3 ; U7.1@35.437,42.474 34.3,42.3 ; U7.1@35.45,42.075 35.45,40.85 ; U7.1@35.625,42.063 35.45,40.85 ; TP13.1@41.6,37.3 39.2,39.7 36.5,39.7 35.45,40.75 U7.1@35.45,42.3 ; C37.1@44.138,36.477 R40.2@45.475,36.8 ; C37.1@44.138,37.123 R40.2@45.475,36.8 ; R40.2@45.71,36.513 C37.1@44.429,37.053 ; R40.2@45.71,37.087 C37.1@44.429,36.547 ; R40.2@45.8,36.775 C37.1@44.429,36.547 ; R40.2@45.8,36.825 C37.1@44.429,37.053 ; R40.2@45.815,36.45 C37.1@44.429,36.547 ; R40.2@45.815,37.15 C37.1@44.429,37.053 ; 34.3,42.3 U7.1@35.45,42.3 ; 34.3,42.3 U7.1@35.45,42.3 ; C37.1@44.425,36.8 R40.2@45.8,36.8 ; C37.1@44.425,36.8 45.762,37.123 C37.1@44.425,36.8 ; C37.1@44.425,36.8 45.762,36.477 C37.1@44.425,36.8 ; C37.1@44.425,36.8 R40.2@45.8,36.8 ; R40.2@45.475,36.8 C37.1@44.1,36.8 R40.2@45.8,36.8
  Top Layer w0.5: TP13.1@41.6,37.3 42.1,36.8 C37.1@44.1,36.8 TP13.1@42.125,36.8
VREG: C2.1 L1.1 R1.2 U2.6 | length 23.7
  Top Layer w0.3: U2.6@19.25,24.7 19.25,28.95 19.5,29.2 19.5,31.1 19.9,31.5 L1.1@22.6,31.5 25.9,31.5 R1.2@26.3,31.1 ; U2.6@19.25,25.375 19.25,26.45 ; C2.1@20.5,31.575 L1.1@21.881,31.5 ; C2.1@20.521,31.251 L1.1@21.881,31.5 ; C2.1@20.556,31.895 L1.1@21.881,31.5 ; C2.1@20.695,31.283 L1.1@21.9,31.5 ; C2.1@20.7,31.5 L1.1@21.9,31.5 ; C2.1@20.699,31.564 L1.1@21.9,31.5 ; L1.1@23.3,31.5 24.5,31.5
VREG_3V3: C1.1 C12.1 C24.1 C30.1 D2.1 D8.1 J4.1 R1.1 R7.2 R9.2 R16.2 R17.2 R32.2 U1.2 U1.16 U4.8 U5.20 U5.45 U6.4 U7.5 U8.3 | length 245.4
  Top Layer w0.3: R9.2@15.626,49.379 v1(14.6,49.7) ; R9.2@15.626,50.021 v1(14.6,49.7) ; R9.2@15.675,49.7 v1(14.6,49.7) ; R9.2@15.7,49.7 v1(14.6,49.7) ; U8.3@16.15,54 U8.3@16.35,53.8 17.8,53.8 18.5,53.1 18.5,52.3 ; R7.2@16.882,45.634 v1(17.2,44.9) ; R7.2@17.518,45.634 v1(17.2,44.9) ; C1.1@18.913,51.173 18.5,52.3 ; C1.1@19.2,51.325 18.5,52.3 ; C1.1@19.436,51.549 18.5,52.3 ; 20.1,51.45 U1.2@21.15,51.45 ; U1.16@21.7,42.35 23.35,42.35 24.3,41.4 v1(24.3,39.6) ; U1.2@21.7,51.45 19.35,51.45 18.5,52.3 ; U1.16@22.25,42.35 23.3,42.35 ; U7.5@36.226,44.941 v1(36.4,45.9) ; U7.5@36.4,44.7 v1(36.4,45.9) ; U7.5@36.4,44.925 v1(36.4,45.9) ; U7.5@36.574,44.941 v1(36.4,45.9) ; C30.1@51.307,25.266 51.75,26.596 ; C30.1@51.6,25.2 51.75,25.35 U6.4@51.75,27.45 ; C30.1@51.625,25.2 51.75,26.596 ; 51.75,26.125 U6.4@51.75,27.225 ; C30.1@51.95,25.209 51.75,26.596 ; v1(55.8,52.1) 56,51.9 56.1,51.9 57.25,50.75 ; U5.20@57.25,49.225 57.25,50.75 ; U5.20@57.25,49.95 57.25,50.75 ; U5.45@65.25,41.25 65.25,40.75 ; U5.45@65.25,41.975 65.25,40.75 ; R17.2@68.2,57.7 v1@69.2,57.7 ; R17.2@68.666,57.382 v1(69.4,57.7) ; R17.2@68.666,58.018 v1(69.4,57.7) ; C24.1@68.882,41.907 69.2,41.2 ; C24.1@69.2,41.975 69.2,41.2 ; C24.1@69.2,42 69.2,41.2 ; C24.1@69.518,41.907 69.2,41.2 ; R16.2@70.134,57.382 v1(69.4,57.7) ; R16.2@70.134,58.018 v1(69.4,57.7) ; v1(17.2,44.9) R7.2@17.2,45.7 v1(17.2,44.9) ; 65.25,40.75 65.575,40.425 68.425,40.425 69.2,41.2 ; R17.2@68.6,57.7 v1@69.2,57.7 ; R17.2@68.6,57.7 v1@69.2,57.7 ; R17.2@68.6,57.7 v1@69.2,57.7 ; R17.2@68.688,57.387 v1@69.2,57.7 ; R17.2@68.688,57.387 v1@69.2,57.7 ; R17.2@68.688,57.387 v1@69.2,57.7 ; R17.2@68.688,57.387 v1@69.2,57.7 ; R17.2@68.688,58.013 v1@69.2,57.7 ; R17.2@68.688,58.013 v1@69.2,57.7 ; R17.2@68.688,58.013 v1@69.2,57.7 ; R17.2@68.688,58.013 v1@69.2,57.7 ; v1@69.2,57.7 v1(69.4,57.7) ; v1(69.4,57.7) R16.2@70.2,57.7 v1(69.4,57.7)
  Top Layer w0.5: U4.8@17.3,62.105 20.895,62.105 C12.1@21,62 v1(23.4,62) ; U4.8@18.1,62.105 19.9,62.105 ; v1@19.014,62.105 C12.1@21,62.025 ; v1(24.3,39.6) 26.3,37.6 R1.1@26.3,35.7 ; 26.7,34.3 v1(28.7,34.3) ; v1(50.4,30.8) 50.4,25.6 50.8,25.2 ; C30.1@51.575,25.2 50.8,25.2 ; C30.1@51.6,25.2 50.8,25.2 ; C24.1@69.2,42 70.471,42 71.7,43.229 v1(71.7,45.6) ; v1(28.7,34.3) R32.2@30.1,34.3 v1(28.7,34.3) ; v1(52.6,52.7) D8.1@52.6,54.2 v1(52.6,52.7)
  Top Layer w1: D2.1@22.6,34.6 24.3,34.6 29.6,34.6
  Bottom Layer w0.3: 14.6,44.8 14.7,44.9 ; v1(55.8,52.1) 55.8,52.7
  Bottom Layer w0.5: J4.1@2.26,41.3 J4.1@2.2,41.24 14.54,41.24 ; 14.7,44.9 v1(17.2,44.9) ; v1(18.9,62.1) 18.4,62.1 18.1,61.8 18.1,54.6 17.5,54 v1(17.3,54) 16.1,52.8 16.1,50.4 15.4,49.7 v1(14.6,49.7) 14.6,44.8 14.6,41.33 16.33,39.6 v1(24.3,39.6) ; v1(28.7,34.3) 33.6,34.3 ; v1(50.4,30.8) 50.4,31.5 49.2,32.7 40.8,32.7 39.2,34.3 33.6,34.3 ; 69.4,53.3 69.4,56.6 v1(69.4,57.7) ; v1(71.7,45.6) 71.7,52.3 70.7,53.3 69.2,53.3 67.3,51.4 65.4,51.4 63.7,49.7 62.5,49.7 59.5,52.7 55.8,52.7 v1(52.6,52.7) 46.4,52.7 42.9,49.2 38.2,49.2 36.4,47.4 v1(36.4,45.9) 34.5,45.9 33.6,45 33.6,34.3
pads on no net: U1.24 U1.31 U1.32 U1.38 U5.22

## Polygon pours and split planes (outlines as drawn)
M1_SL on Top Layer "Top Layer-No Net 17" (solid, pour order 42): 75.7,21.8 72.8,21.8 72.6,22 72.6,23.8 72.6,24.2 72.8,24.4 73.6,24.4 73.7,24.3 73.7,23.9 73.7,23.7 74.5,22.9 75.8,22.9
GND_IN on Top Layer "Top Layer-No Net 14" (solid, pour order 62): 80.1,60.9 80.1,50.9 83.815,47.185 87.185,47.185 87.6,47.6 87.6,56.9 83,61.5 80.7,61.5
VM on Top Layer "Top Layer-No Net 10" (solid, pour order 49): 70.1,18.5 73.1,15.5 76.6,15.5 77.4,14.7 77.4,9.9 78.2,9 81.6,9 84,11.4 84,35.1 78.1,41 78.1,61.464 77.517,62.1 74.611,62.1 74,61.55 74,38.942 79.005,33.786 78.991,23.491 76.5,21 70.1,21
GND on Top Layer "Top Layer-No Net 16" (solid, pour order 40): 74.2,24.7 74.2,23.8 74.5,23.5 78,23.5 78.2,23.7 78.3,23.8 78.3,25 78.3,26.1 77.3,25.1 77.3,25
VM on Top Layer "Top Layer-No Net 11" (solid, pour order 43): 58.6,21 60.6,21 61.629,22.2 63.2,22.2 63.2,19.119 61.7,17.619 59.4,17.619 58.5,18.519 58.5,20.319
M1_SL on Top Layer "Top Layer-No Net 12" (solid, pour order 50): 69.275,25.931 69.275,26.331 69.575,26.631 69.575,28.631 69.3,28.9 68.4,28.9 68.1,29.4 67.975,28.231 67.975,27.131 69.075,26.031 69.075,25.931
GND on Top Layer "Top Layer-GND2" (solid, remove dead copper, pour order 70): 78.6,49 78.6,42.2 84.1,36.7 85.2,35.6 85.2,27.1 85.2,10.4 86.1,9.5 86.4,9.2 91.8,9.2 92.8,10.2 92.8,10.6 92.8,48.8 91.9,49.7 79.5,49.7 78.6,48.8
GND on Top Layer "Top Layer-gnd" (solid, remove dead copper, pour order 67): 0.886,42.522 6.286,42.522 11.186,47.422 11.186,51.822 14.986,55.622 16.186,56.822 16.186,62.322 16.186,62.922 17.086,63.822 17.786,64.522 70.986,64.522 72.486,63.022 72.486,47.422 72.486,33.222 71.686,32.422 69.886,30.622 53.986,30.622 40.386,30.622 38.286,28.522 32.286,22.522 28.786,22.522 25.586,22.522 22.686,19.622 21.586,18.522 17.986,18.522 15.386,15.922 13.286,15.922 2.786,15.922 0.986,17.722
M1_SL on Top Layer "Top Layer-No Net 15" (solid, pour order 63): 77.6,30 77.6,32.1 76.7,33 72.5,33 72.3,32.8 72.2,32.7 72.2,30.6 72.2,30.3 72.7,29.8 72.7,27 73.1,26.6 73.7,26.6 77.2,26.6 77.6,27
M1_OUT_A on Top Layer "Top Layer-No Net 5" (solid, pour order 41): 69.3,21.8 64.9,21.8 64.4,21.3 64.4,14.6 65,14 70.2,14 70.8,14.6 70.8,17 69.4,18.4 69.4,21.6
M1_OUT_B on Top Layer "Top Layer-No Net 4" (solid, pour order 40): 57.6,21.1 52.7,21.1 52.3,20.7 52.3,14.9 53.2,14 59.3,14 59.5,14.2 59.5,16.5 57.8,18.2 57.8,20.9
M1_OUT_C on Top Layer "Top Layer-No Net 3" (solid, pour order 39): 42.9,21.5 38.7,21.5 38.1,20.9 38.1,14.6 38.8,13.9 48.1,13.9 48.4,14.2 48.4,17.1 48.2,17.3 44.1,17.3 43.1,18.3 43.1,21.4
NetJ8_1 on Top Layer "Top Layer-No Net 1" (solid, pour order 37): 63.4,12.65 61,10.25 61,3 61.5,2.5 68.7,2.5 69.8,3.6 69.8,12.15 69.3,12.65
NetJ8_3 on Top Layer "Top Layer-No Net 2" (solid, pour order 38): 49,12.6 53.4,8.2 53.4,3.4 52.5,2.5 43.3,2.5 42.7,3.1 42.7,12.3 43,12.6
M1_OUT_A on Top Layer "Top Layer-No Net 13" (solid, pour order 53): 71.31,25.166 71.31,24.066 71.044,23.8 65.744,23.8 64.41,22.466 64.41,20.766 69.21,20.766 69.41,20.966 69.41,21.366 69.6,21.6 71.3,21.6 72.01,22.366 72.01,25.047 71.625,25.432
M1_OUT_C on Top Layer "Top Layer-No Net 13" (solid, pour order 54): 45,25.1 45,24 44.8,23.8 39.5,23.8 38.1,22.4 38.1,20.7 42.9,20.7 43.1,20.9 43.1,21.3 43.4,21.6 45,21.6 45.7,22.3 45.7,24.981 45.315,25.366
M1_OUT_B on Top Layer "Top Layer-No Net 13" (solid, pour order 55): 59.71,25.166 59.71,24.066 59.4,23.7 54.1,23.7 52.3,21.956 52.3,20.1 56.944,20.1 57.81,20.966 57.81,21.366 58.044,21.6 59.9,21.6 60.41,22.11 60.41,25.047 60.025,25.432
M1_SL on Top Layer "Top Layer-No Net 12" (solid, pour order 51): 57.675,25.931 57.675,26.331 57.975,26.631 57.975,27.631 57.975,28.631 57.675,28.931 57.075,28.931 56.375,28.231 56.375,27.131 56.875,26.631 57.475,26.031 57.475,25.931
M1_SL on Top Layer "Top Layer-No Net 12" (solid, pour order 52): 43,25.9 43,26.3 43.3,26.6 43.3,27.6 43.3,28.6 43,28.9 42.4,28.9 41.7,28.2 41.7,27.1 42.2,26.6 42.8,26 42.8,25.9
VM on Top Layer "Top Layer-No Net 11" (solid, pour order 44): 43.8,21 45.3,21 45.9,21.6 48.5,21.6 48.5,18.5 47.984,17.984 44.7,17.984 43.8,18.884 43.8,20.684
VM on Top Layer "Top Layer-No Net 9" (solid, pour order 48): 21.7,19.6 21.7,17.6 22.4,16.9 26.7,16.9 35.6,16.9 36.3,17.6 36.3,19.8 35.6,20.5 27.9,20.5 27.1,19.7 21.9,19.7 21.8,19.6
NetL3_1 on Top Layer "Top Layer-No Net 6" (solid, pour order 42): 19.1,19.5 19.1,16.1 18.7,15.7 18.5,15.5 18.5,13.5 18.5,13.3 18.6,13.2 20.1,13.2 20.4,13.5 20.4,16.9 20.1,17.2 20.1,19.2 20.1,19.5 19.9,19.7 19.2,19.7
NetL2_1 on Top Layer "Top Layer-No Net 7" (solid, pour order 45): 20.4,19.6 20.4,17.4 20.8,17 20.8,15.3 20.8,14.2 21.5,13.5 21.8,13.2 24,13.2 24.9,13.2 25.1,13.4 25.1,15.1 24.2,16 22.9,16 21.4,17.5 21.4,18.9 21.4,19.6 21.3,19.7 20.5,19.7
NetL4_1 on Top Layer "Top Layer-No Net 8" (solid, pour order 46): 18.8,19.6 18.8,16.5 18,15.7 17.8,15.5 17.8,13.9 17.8,13.6 17.4,13.2 15.9,13.2 13.4,13.2 13.3,13.3 13.3,14.6 13.5,14.8 13.7,15 15,15 15.5,15 17.7,17.2 17.8,17.3 17.8,18.9 17.8,19.6 17.9,19.7 18.7,19.7
NetJ8_2 on Top Layer "Top Layer-No Net" (solid, pour order 36): 59,3.05 58.3,2.35 56.1,2.35 55.5,2.95 55.5,9.75 53.6,11.65 53.6,12.45 53.9,12.65 58.6,12.65 59,12.55
GND on Bottom Layer "Bottom Layer-No Net 4" (solid, pour order 38): 74.9,25.2 74.9,29 75.6,29.7 84.4,29.7 85.4,30.7 85.4,17.8 81.4,21.8 75.3,21.8 74.9,22.2 74.9,25.2
VM on Bottom Layer "Bottom Layer-No Net 1" (solid, pour order 47): 44.6,22.8 70.5,22.8 72.2,21.1 75.2,21.1 75.6,20.7 75.6,18.8 75.2,18.5 70.7,18.5 68.9,20.3 50.076,20.3 48.448,18.5 44.05,18.5 43.6,18.9 43.6,21.8
VM on Bottom Layer "Bottom Layer-No Net 2" (solid, pour order 60): 62.4,18.2 61.8,17.6 59.345,17.6 58.4,18.5 58.4,19.9 57.5,20.8 63.2,20.8 62.4,20
M1_OUT_A on Bottom Layer "Bottom Layer-No Net" (solid, pour order 56): 68.5,19.2 70.8,16.9 70.8,14.6 70.2,14 63.9,14 63.4,14.5 63.4,18.2 64.4,19.2
M1_OUT_B on Bottom Layer "Bottom Layer-No Net" (solid, pour order 58): 56.7,19.4 59.5,16.6 59.5,14.6 58.9,14 52.6,14 52.1,14.5 52.1,18.8 52.7,19.4
M1_SL on Bottom Layer "Bottom Layer-No Net 3" (solid, pour order 64): 73.9,30 42.5,30 41.45,28.95 41.45,24.1 42.15,23.4 71.2,23.4 73,21.6 74.4,21.6 74.35,24.6 74.4,29.5
GND on Bottom Layer "Bottom Layer-GND" (solid, remove dead copper, pour order 66): 0.873,42.367 6.273,42.367 11.173,47.267 11.173,51.667 16.173,56.667 16.173,62.767 17.773,64.367 70.973,64.367 72.473,62.867 72.473,33.067 69.873,30.467 40.373,30.467 35.473,25.567 35.473,22.367 25.573,22.367 21.573,18.367 17.973,18.367 15.373,15.767 2.773,15.767 0.973,17.567
GND on Bottom Layer "Bottom Layer-GND2" (solid, remove dead copper, pour order 69): 78.5,49 78.5,42.2 84,36.7 85.1,35.6 85.1,27.1 85.1,10.4 86,9.5 86.3,9.2 91.7,9.2 92.7,10.2 92.7,10.6 92.7,48.8 91.8,49.7 79.4,49.7 78.5,48.8
VM on Bottom Layer "Bottom Layer-No Net 5" (solid, pour order 68): 27.2,21.5 28.3,20.4 32.6,20.4 33.8,20.4 34.4,19.8 34.4,17.2 34.4,16.5 34.1,16.2 33.9,16 33.1,16 32.2,16.9 29.9,16.9 25,16.9 24.7,17.2 24.7,19.7 26.1,21.1
M1_OUT_C on Bottom Layer "Bottom Layer-No Net" (solid, pour order 57): 48,17.2 48.4,16.8 48.4,14.5 47.8,13.9 38.9,13.9 38.2,14.6 38.2,20.4 39,21.2 42.3,21.2 42.8,20.7 42.8,18 43.6,17.2
VM on Bottom Layer "Bottom Layer-No Net 2" (solid, pour order 59): 75.5,18.8 74.5,17.8 70.9,17.8 70.8,17.8 70.2,18.4 70.2,20.55 70.65,21 71.15,20.5 72.7,20.5
VM on Bottom Layer "Bottom Layer-No Net 2" (solid, pour order 61): 48.9,18.9 47.9,17.9 44.3,17.9 44.2,17.9 43.6,18.5 43.6,20.65 44.05,21.1 44.55,20.6 46.1,20.6

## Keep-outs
Keep-Out Layer:
  circle w0.254: c4,4 r1.75
  circle w0.254: c90,4 r1.75
  circle w0.254: c90,61 r1.75
  circle w0.254: c4,61 r1.75
  lines w0.2: 0,0 0,65 94,65 94,0 0,0

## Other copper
Top Layer:
  rectangle net M1_SL: 61.5,23.4 64.1,26.6
  rectangle net M1_SL: 72.7,21.8 74.2,23.1
  rectangle net GND: 80.1,41 82.1,44.5
  rectangle net GND: 81.2,44.4 82.5,47.4
  rectangle net GND: 84.225,45.3 85.5,46.56
  rectangle net GND: 83.1,41.2 84.5,46.4
  rectangle net GND: 16.5,18.8 17.4,20.5
  rectangle net M1_SL: 46.9,23.4 49.4,26.4
  rectangle net GND: 30.1,23 33.8,25
  rectangle net GND: 84.8,32.1 91.2,33.8
  rectangle net GND: 85.1,14 91.3,15.4
  rectangle net GND: 86.8,12 89.3,17.6
  rectangle net GND: 86.8,30.3 89.3,35.5
  rectangle net GND: 65.6,41.975 66.25,43.6
  rectangle net VM: 25.6,16.9 32.1,19.7
  region net GND: 52.5,47.2 52.5,43.3 67.9,43.3 67.9,47.2
  region net GND: 14.5,23.3 14.5,20.3 23.2,20.3 23.2,23.3
  region net GND: 84,46.4 84,44.5 84.8,44.5 84.8,46.4
  pour cut-out: 16,17.8 17.9,17.8 17.8,17.7 17.8,16.3 17,15.5 12.6,15.5 12.6,16.8 13.2,17.4
Bottom Layer:
  rectangle net GND: 78.5,34.4 85.9,43
  rectangle net GND: 71.2,32.2 87.3,44.3

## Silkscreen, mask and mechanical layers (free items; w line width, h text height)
Top Overlay:
  circle w0.254: c90,61 r3
  circle w0.254: c89.9,4 r3
  circle w0.254: c4,4 r3
  circle w0.254: c4,61 r3
  lines w0.2: 43.1,54.9 43.5,55.3 ; 43.5,47.2 43.5,55.3 ; 43.9,54.9 43.5,55.3 ; 38.8,56.3 38.8,63 39,63.2 44.9,63.2 45.6,62.5 45.6,56.6 44.8,55.8 39.3,55.8 38.8,56.3 ; 42.9,40.3 42.9,47.2 49.9,47.2 50,47.1 50,39.9 43.3,39.9 42.9,40.3
  text "VM" at 75.8,55.3 h1.02
  text "GND" at 81.7,55.3 h1.02
  text "TX_ISO" at 3.7,49.4 h1.02
  text "RX_ISO" at 3.9,46.8 h1.02
  text "3V3" at 4.5,40.8 h1.02
  text "Test" at 4.5,38 h1.02
  text "RST" at 4.7,35.6 h1.02
  text "GND" at 4,30.9 h0.8 r270
  text "SDA" at 3.9,26.8 h0.8
  text "SCL" at 3.9,24.1 h0.8
  text "Texas" at 34.7,5.9 h1.5
  text "Instruments" at 35.2,3.6 h1.5
  text "TIDA-00447 E1" at 69.1,2.4 h1.5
